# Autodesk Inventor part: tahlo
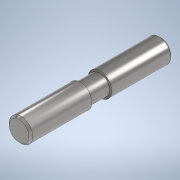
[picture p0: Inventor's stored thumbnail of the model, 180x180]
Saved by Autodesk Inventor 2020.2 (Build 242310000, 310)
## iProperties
Created: 2020-04
Part Number: tahlo
Material: Stainless Steel
Document SubType Name: Modeling
Designer: freem
Density: 8 g/cm^3
Appearance: Semi-Polished
Author: freem
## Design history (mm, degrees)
sketch "Sketch1"
  geometry: L1 (0, -15.437)-(0, 42.264); L2 (5, 0)-(0, 0); L3 (5, 0)-(5, 5); L4 (5, 5)-(6, 5); L5 (6, 5)-(6, 36); L6 (6, 36)-(0, 36)
  constraints: 12 end point, 3 perpendicular, 2 point on line, 2 vertical, 1 horizontal
  dimensions: "d0" = 5 distance between parallel lines of L2 L4; "d1" = 31 distance between parallel lines of L4 L6; "d2" = 12 diameter of L5 L1; "d3" = 10 diameter of L3 L1
revolve "Revolution1" sketch "Sketch1" stored, may be unused: angle "d4" = 90 deg
chamfer "Chamfer1" distance "d5" = 1; stored, may be unused: second distance "d6" = 2, angle "d7" = 45 deg
mirror "Mirror1"
body "Solid1"
